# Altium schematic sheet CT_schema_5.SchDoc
size 284 x 211 mm
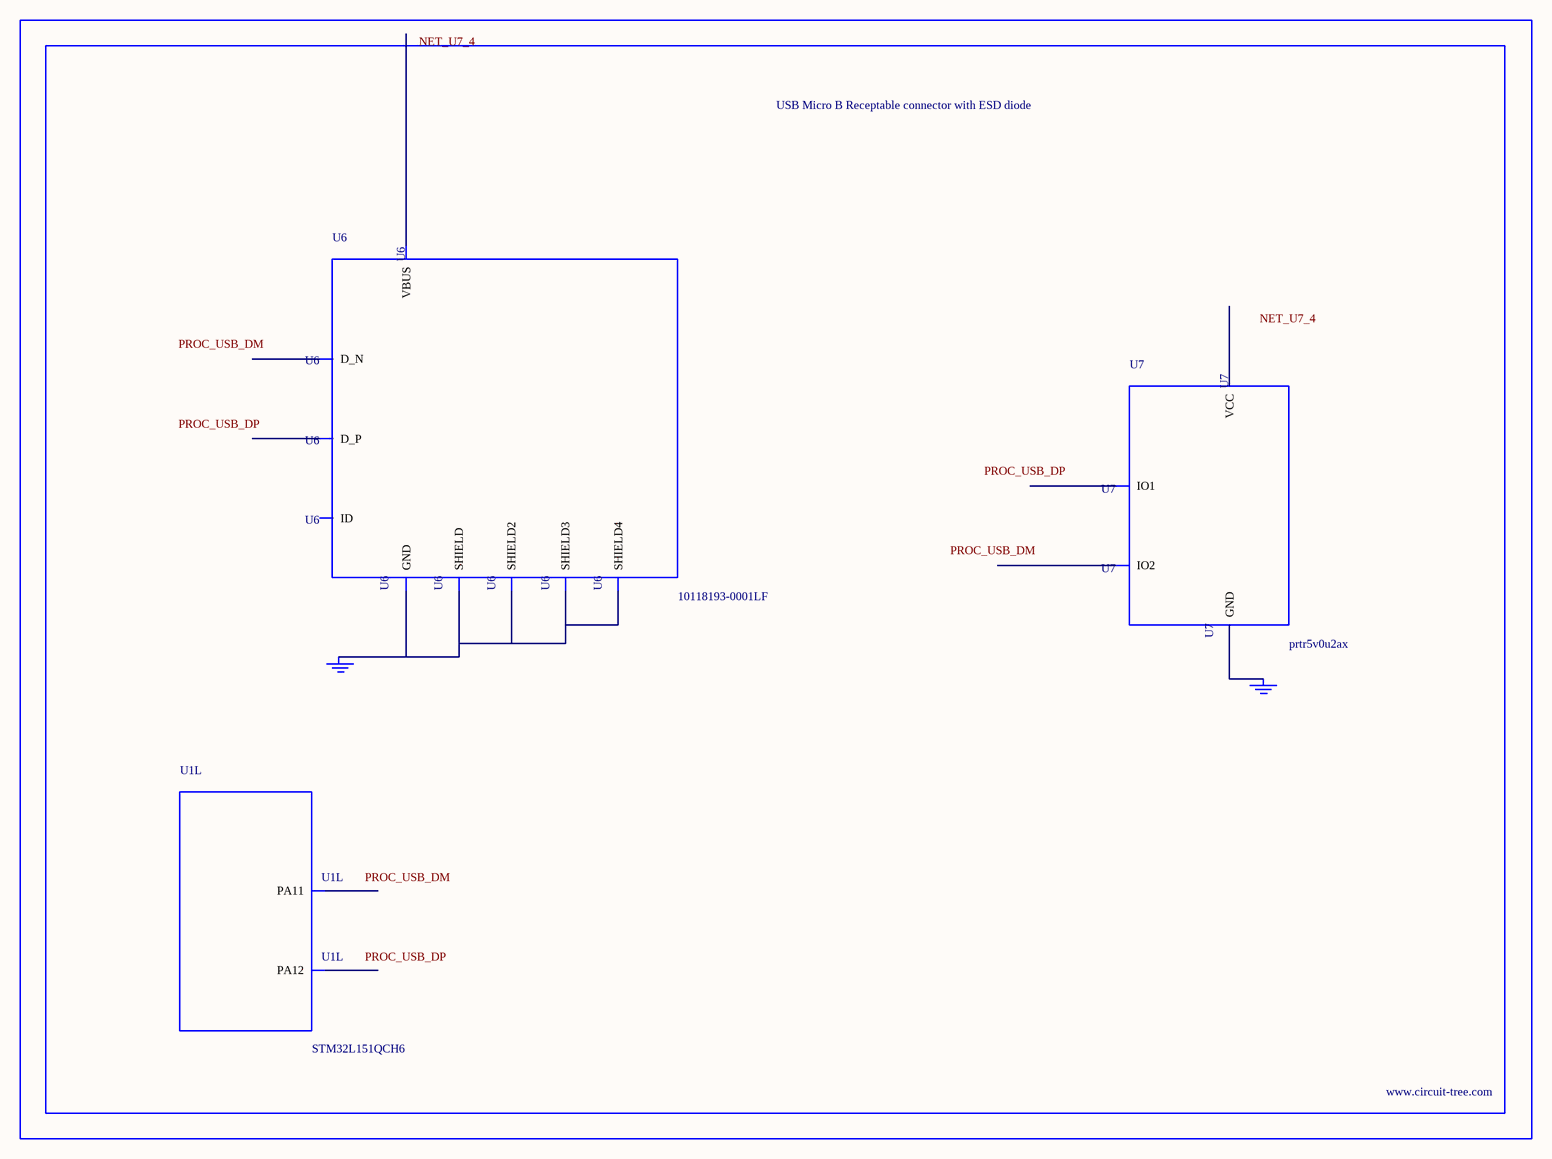
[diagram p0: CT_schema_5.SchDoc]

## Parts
BORDER4  (no value)
GND_INSTANCE_4_0  (no value)
GND_INSTANCE_4_1  (no value)
U1  STM32L151QCH6  [UFBGA132]  (part L of 12)
U6  10118193-0001LF  [FCI_10118193-0001LF]
U7  prtr5v0u2ax  [SOT143B]

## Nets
NetGND_INSTANCE_4_0_0: GND_INSTANCE_4_0.0(GND) U6.5(GND) U6.6(SHIELD) U6.7(SHIELD2) U6.8(SHIELD3) U6.9(SHIELD4)
NetGND_INSTANCE_4_1_0: GND_INSTANCE_4_1.0(GND) U7.1(GND)

Not connected (* = marked no-connect by the designer): U1 A12(PA12) B12(PA11); U6 1(VBUS) 2(D_N) 3(D_P) 4(ID); U7 2(IO1) 3(IO2) 4(VCC)

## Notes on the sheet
- Labels drawn without touching a wire or pin: NET_U7_4, PROC_USB_DM, PROC_USB_DP

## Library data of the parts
BORDER4 = BORDER_PAGE4
GND_INSTANCE_4_0 GND_INSTANCE_4_1 = GND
